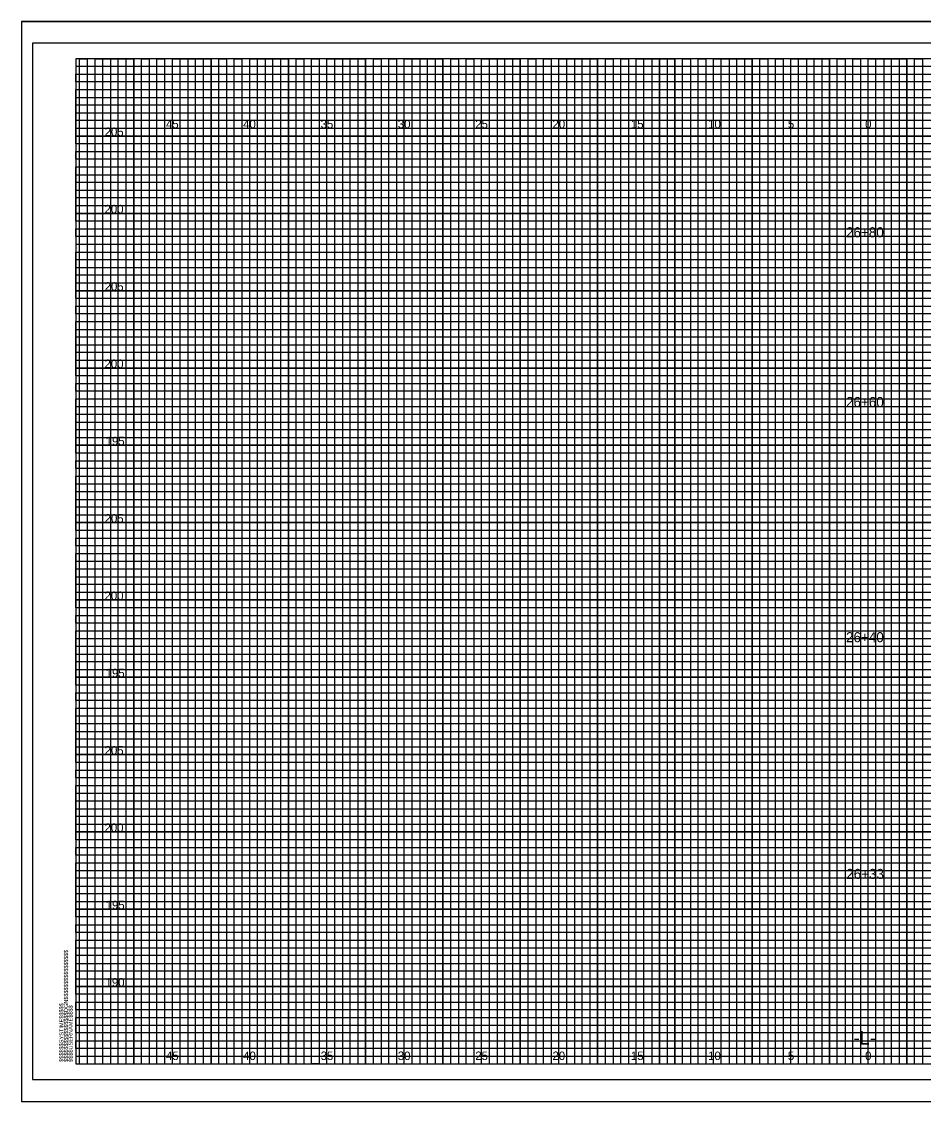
# Model space of a CAD drawing. Extents: x -4 to 103, y -2 to 6583.
# Drawn here: x -3.5 to 54.8, y 1626.6 to 1696.4 of the extents above; entities that cross this region are included whole.
import ezdxf

# ---------------------------------------------------------------- set-up
doc = ezdxf.new("R2010")
doc.units = 0
for name, color, linetype in [('Prop XS Alignment Label', 7, 'Continuous'), ('Prop XS Elevation Labels', 7, 'Continuous'), ('Prop XS Offset Labels', 7, 'Continuous'), ('Prop XS Station Labels', 7, 'Continuous'), ('Sheet Cross Section CELL', 7, 'Continuous'), ('Sheet Cross Section Grid Major CELL', 7, 'Continuous'), ('Sheet Cross Section Grid Middle CELL', 7, 'Continuous'), ('Sheet Cutting Line CELL', 7, 'Continuous'), ('Sheet DOT Grid CELL', 7, 'Continuous'), ('Sheet Plot Border Inside CELL', 7, 'Continuous'), ('Sheet Plot Border Outside CELL', 7, 'Continuous')]:
    doc.layers.add(name, color=color, linetype=linetype)

msp = doc.modelspace()

# ---------------------------------------------------------------- linework, layer by layer
at = {"layer": 'Sheet Cross Section CELL'}
msp.add_lwpolyline([(102.5, 1693.975), (0, 1693.975), (0, 1628.975), (102.5, 1628.975)], close=True, dxfattribs=at)
at = {"layer": 'Sheet Cross Section Grid Major CELL'}
for points in [[(1.25, 1628.975), (1.25, 1693.975), (3.75, 1693.975), (3.75, 1628.975), (6.25, 1628.975), (6.25, 1693.975), (8.75, 1693.975), (8.75, 1628.975), (11.25, 1628.975), (11.25, 1693.975), (13.75, 1693.975), (13.75, 1628.975), (16.25, 1628.975), (16.25, 1693.975), (18.75, 1693.975), (18.75, 1628.975), (21.25, 1628.975), (21.25, 1693.975), (23.75, 1693.975), (23.75, 1628.975), (26.25, 1628.975), (26.25, 1693.975), (28.75, 1693.975), (28.75, 1628.975), (31.25, 1628.975), (31.25, 1693.975), (33.75, 1693.975), (33.75, 1628.975), (36.25, 1628.975), (36.25, 1693.975), (38.75, 1693.975), (38.75, 1628.975), (41.25, 1628.975), (41.25, 1693.975), (43.75, 1693.975), (43.75, 1628.975), (46.25, 1628.975), (46.25, 1693.975), (48.75, 1693.975), (48.75, 1628.975), (51.25, 1628.975), (51.25, 1693.975), (53.75, 1693.975), (53.75, 1628.975)], [(102.5, 1688.975), (0, 1688.975), (0, 1691.475), (74.25, 1691.475)], [(102.5, 1683.975), (0, 1683.975), (0, 1686.475), (102.5, 1686.475)], [(102.5, 1678.975), (0, 1678.975), (0, 1681.475), (102.5, 1681.475)], [(102.5, 1673.975), (0, 1673.975), (0, 1676.475), (102.5, 1676.475)], [(102.5, 1668.975), (0, 1668.975), (0, 1671.475), (102.5, 1671.475)], [(102.5, 1663.975), (0, 1663.975), (0, 1666.475), (102.5, 1666.475)], [(102.5, 1658.975), (0, 1658.975), (0, 1661.475), (102.5, 1661.475)], [(102.5, 1653.975), (0, 1653.975), (0, 1656.475), (102.5, 1656.475)], [(102.5, 1648.975), (0, 1648.975), (0, 1651.475), (102.5, 1651.475)], [(102.5, 1643.975), (0, 1643.975), (0, 1646.475), (102.5, 1646.475)], [(102.5, 1638.975), (0, 1638.975), (0, 1641.475), (102.5, 1641.475)], [(102.5, 1633.975), (0, 1633.975), (0, 1636.475), (102.5, 1636.475)], [(0, 1631.475), (102.5, 1631.475)]]:
    msp.add_lwpolyline(points, dxfattribs=at)
at = {"layer": 'Sheet Cross Section Grid Middle CELL'}
for points in [[(0.25, 1628.975), (0.25, 1693.975), (0.75, 1693.975), (0.75, 1628.975), (1.75, 1628.975), (1.75, 1693.975), (2.25, 1693.975), (2.25, 1628.975), (2.75, 1628.975), (2.75, 1693.975), (3.25, 1693.975), (3.25, 1628.975), (4.25, 1628.975), (4.25, 1693.975), (4.75, 1693.975), (4.75, 1628.975), (5.25, 1628.975), (5.25, 1693.975), (5.75, 1693.975), (5.75, 1628.975), (6.75, 1628.975), (6.75, 1693.975), (7.25, 1693.975), (7.25, 1628.975), (7.75, 1628.975), (7.75, 1693.975), (8.25, 1693.975), (8.25, 1628.975), (9.25, 1628.975), (9.25, 1693.975), (9.75, 1693.975), (9.75, 1628.975), (10.25, 1628.975), (10.25, 1693.975), (10.75, 1693.975), (10.75, 1628.975), (11.75, 1628.975), (11.75, 1693.975), (12.25, 1693.975), (12.25, 1628.975), (12.75, 1628.975), (12.75, 1693.975), (13.25, 1693.975), (13.25, 1628.975), (14.25, 1628.975), (14.25, 1693.975), (14.75, 1693.975), (14.75, 1628.975), (15.75, 1628.975), (15.25, 1628.975), (15.25, 1693.975), (15.75, 1693.975), (15.75, 1628.975), (16.75, 1628.975), (16.75, 1693.975), (17.25, 1693.975), (17.25, 1628.975), (17.75, 1628.975), (17.75, 1693.975), (18.25, 1693.975), (18.25, 1628.975), (19.25, 1628.975), (19.25, 1693.975), (19.75, 1693.975), (19.75, 1628.975), (20.25, 1628.975), (20.25, 1693.975), (20.75, 1693.975), (20.75, 1628.975), (21.75, 1628.975), (21.75, 1693.975), (22.25, 1693.975), (22.25, 1628.975), (22.75, 1628.975), (22.75, 1693.975), (23.25, 1693.975), (23.25, 1628.975), (24.25, 1628.975), (24.25, 1693.975), (24.75, 1693.975), (24.75, 1628.975), (25.25, 1628.975), (25.25, 1693.975), (25.75, 1693.975), (25.75, 1628.975), (26.75, 1628.975), (26.75, 1693.975), (27.25, 1693.975), (27.25, 1628.975), (27.75, 1628.975), (27.75, 1693.975), (28.25, 1693.975), (28.25, 1628.975), (29.25, 1628.975), (29.25, 1693.975), (29.75, 1693.975), (29.75, 1628.975), (30.25, 1628.975), (30.25, 1693.975), (30.75, 1693.975), (30.75, 1628.975)], [(30.75, 1628.975), (31.75, 1628.975), (31.75, 1693.975), (32.25, 1693.975), (32.25, 1628.975), (32.75, 1628.975), (32.75, 1693.975), (33.25, 1693.975), (33.25, 1628.975), (34.25, 1628.975), (34.25, 1693.975), (34.75, 1693.975), (34.75, 1628.975), (35.25, 1628.975), (35.25, 1693.975), (35.75, 1693.975), (35.75, 1628.975), (36.75, 1628.975), (36.75, 1693.975), (37.25, 1693.975), (37.25, 1628.975), (37.75, 1628.975), (37.75, 1693.975), (37.75, 1628.975)], [(38.25, 1693.975), (38.25, 1628.975), (39.25, 1628.975), (39.25, 1693.975), (39.75, 1693.975), (39.75, 1628.975), (40.25, 1628.975), (40.25, 1693.975), (40.75, 1693.975), (40.75, 1628.975), (41.75, 1628.975), (41.75, 1693.975), (42.25, 1693.975), (42.25, 1628.975), (42.75, 1628.975), (42.75, 1693.975), (43.25, 1693.975), (43.25, 1628.975), (43.75, 1628.975), (44.25, 1628.975), (44.25, 1693.975), (44.75, 1693.975), (44.75, 1628.975), (45.25, 1628.975), (45.25, 1693.975), (45.75, 1693.975), (45.75, 1628.975), (46.75, 1628.975), (46.75, 1693.975), (47.25, 1693.975), (47.25, 1628.975), (47.75, 1628.975), (47.75, 1693.975), (48.25, 1693.975), (48.25, 1628.975), (49.25, 1628.975), (49.25, 1693.975), (49.75, 1693.975), (49.75, 1628.975), (50.25, 1628.975), (50.25, 1693.975), (50.75, 1693.975), (50.75, 1628.975), (51.75, 1628.975), (51.75, 1693.975), (52.25, 1693.975), (52.25, 1628.975), (52.75, 1628.975), (52.75, 1693.975), (53.25, 1693.975), (53.25, 1628.975), (54.25, 1628.975), (54.25, 1693.975), (54.75, 1693.975), (54.75, 1628.975), (55.25, 1628.975)], [(0, 1690.975), (0, 1691.975), (74.25, 1691.975), (74.25, 1692.475), (0, 1692.475), (0, 1692.975), (74.25, 1692.975), (74.25, 1693.475), (0, 1693.475)], [(102.5, 1690.975), (0, 1690.975)], [(102.5, 1689.975), (0, 1689.975), (0, 1690.475), (102.5, 1690.475)], [(102.5, 1688.475), (0, 1688.475), (0, 1689.475), (102.5, 1689.475)], [(102.5, 1687.475), (0, 1687.475), (0, 1687.975), (102.5, 1687.975)], [(102.5, 1685.975), (0, 1685.975), (0, 1686.975), (102.5, 1686.975)], [(102.5, 1684.975), (0, 1684.975), (0, 1685.475), (102.5, 1685.475)], [(102.5, 1683.475), (0, 1683.475), (0, 1684.475), (102.5, 1684.475)], [(102.5, 1682.475), (0, 1682.475), (0, 1682.975), (102.5, 1682.975)], [(0, 1681.975), (102.5, 1681.975)], [(102.5, 1680.975), (0, 1680.975)], [(102.5, 1679.975), (0, 1679.975), (0, 1680.475), (102.5, 1680.475)], [(102.5, 1678.475), (0, 1678.475), (0, 1679.475), (102.5, 1679.475)], [(102.5, 1677.475), (0, 1677.475), (0, 1677.975), (102.5, 1677.975)], [(102.5, 1675.975), (0, 1675.975), (0, 1676.975), (102.5, 1676.975)], [(102.5, 1674.975), (0, 1674.975), (0, 1675.475), (102.5, 1675.475)], [(102.5, 1673.475), (0, 1673.475), (0, 1674.475), (102.5, 1674.475)], [(102.5, 1672.475), (0, 1672.475), (0, 1672.975), (102.5, 1672.975)], [(102.5, 1670.975), (0, 1670.975), (0, 1671.975), (102.5, 1671.975)], [(102.5, 1669.975), (0, 1669.975), (0, 1670.475), (102.5, 1670.475)], [(102.5, 1668.475), (0, 1668.475), (0, 1669.475), (102.5, 1669.475)], [(102.5, 1667.475), (0, 1667.475), (0, 1667.975), (102.5, 1667.975)], [(102.5, 1665.975), (0, 1665.975), (0, 1666.975), (102.5, 1666.975)], [(102.5, 1664.975), (0, 1664.975), (0, 1665.475), (102.5, 1665.475)], [(102.5, 1663.475), (0, 1663.475), (0, 1664.475), (102.5, 1664.475)], [(102.5, 1662.475), (0, 1662.475), (0, 1662.975), (102.5, 1662.975)], [(102.5, 1660.975), (0, 1660.975), (0, 1661.975), (102.5, 1661.975)], [(102.5, 1659.975), (0, 1659.975), (0, 1660.475)], [(0, 1660.475), (102.5, 1660.475)], [(102.5, 1658.475), (0, 1658.475), (0, 1659.475), (102.5, 1659.475)], [(102.5, 1657.475), (0, 1657.475), (0, 1657.975), (102.5, 1657.975)], [(102.5, 1655.975), (0, 1655.975), (0, 1656.975), (102.5, 1656.975)], [(102.5, 1654.975), (0, 1654.975), (0, 1655.475), (102.5, 1655.475)], [(102.5, 1653.475), (0, 1653.475), (0, 1654.475), (102.5, 1654.475)], [(102.5, 1652.475), (0, 1652.475), (0, 1652.975), (102.5, 1652.975)], [(102.5, 1650.975), (0, 1650.975), (0, 1651.975), (102.5, 1651.975)], [(102.5, 1649.975), (0, 1649.975), (0, 1650.475), (102.5, 1650.475)], [(102.5, 1648.475), (0, 1648.475), (0, 1649.475), (102.5, 1649.475)], [(102.5, 1647.475), (0, 1647.475), (0, 1647.975), (102.5, 1647.975)], [(102.5, 1645.975), (0, 1645.975), (0, 1646.975), (102.5, 1646.975)], [(102.5, 1644.975), (0, 1644.975), (0, 1645.475), (102.5, 1645.475)], [(102.5, 1643.475), (0, 1643.475), (0, 1644.475), (102.5, 1644.475)], [(102.5, 1642.475), (0, 1642.475), (0, 1642.975), (102.5, 1642.975)], [(102.5, 1640.975), (0, 1640.975), (0, 1641.975), (102.5, 1641.975)], [(102.5, 1639.975), (0, 1639.975), (0, 1640.475), (102.5, 1640.475)], [(102.5, 1638.475), (0, 1638.475), (0, 1639.475), (102.5, 1639.475)], [(102.5, 1637.475), (0, 1637.475), (0, 1637.975), (102.5, 1637.975)], [(102.5, 1635.975), (0, 1635.975), (0, 1636.975), (102.5, 1636.975)], [(102.5, 1634.975), (0, 1634.975), (0, 1635.475), (102.5, 1635.475)], [(102.5, 1633.475), (0, 1633.475), (0, 1634.475), (102.5, 1634.475)], [(102.5, 1632.475), (0, 1632.475), (0, 1632.975), (102.5, 1632.975)], [(102.5, 1630.975), (0, 1630.975), (0, 1631.975), (102.5, 1631.975)], [(102.5, 1629.975), (0, 1629.975), (0, 1630.475), (102.5, 1630.475)], [(0, 1629.475), (102.5, 1629.475)]]:
    msp.add_lwpolyline(points, dxfattribs=at)
at = {"layer": 'Sheet Cutting Line CELL'}
for p, q in [((-3.5, 1696.375), (103.4, 1696.375)), ((-3.5, 1696.375), (-3.5, 1626.55)), ((-3.5, 1626.55), (103.4, 1626.55))]:
    msp.add_line(p, q, dxfattribs=at)
at = {"layer": 'Sheet DOT Grid CELL'}
for p, q in [((1.25, 1628.975), (1.25, 1693.975)), ((3.75, 1628.975), (3.75, 1693.975)), ((6.25, 1628.975), (6.25, 1693.975)), ((8.75, 1628.975), (8.75, 1693.975)), ((11.25, 1628.975), (11.25, 1693.975)), ((13.75, 1628.975), (13.75, 1693.975)), ((16.25, 1628.975), (16.25, 1693.975)), ((18.75, 1628.975), (18.75, 1693.975)), ((21.25, 1628.975), (21.25, 1693.975)), ((23.75, 1628.975), (23.75, 1693.975)), ((26.25, 1628.975), (26.25, 1693.975)), ((28.75, 1628.975), (28.75, 1693.975)), ((31.25, 1628.975), (31.25, 1693.975)), ((33.75, 1628.975), (33.75, 1693.975)), ((36.25, 1628.975), (36.25, 1693.975)), ((38.75, 1628.975), (38.75, 1693.975)), ((41.25, 1628.975), (41.25, 1693.975)), ((43.75, 1628.975), (43.75, 1693.975)), ((46.25, 1628.975), (46.25, 1693.975)), ((48.75, 1628.975), (48.75, 1693.975)), ((51.25, 1628.975), (51.25, 1693.975)), ((53.75, 1628.975), (53.75, 1693.975)), ((0, 1691.475), (74.25, 1691.475)), ((0, 1688.975), (102.5, 1688.975)), ((0, 1686.475), (102.5, 1686.475)), ((0, 1683.975), (102.5, 1683.975)), ((0, 1681.475), (102.5, 1681.475)), ((0, 1678.975), (102.5, 1678.975)), ((0, 1676.475), (102.5, 1676.475)), ((0, 1673.975), (102.5, 1673.975)), ((0, 1671.475), (102.5, 1671.475)), ((0, 1668.975), (102.5, 1668.975)), ((0, 1666.475), (102.5, 1666.475)), ((0, 1663.975), (102.5, 1663.975)), ((0, 1661.475), (102.5, 1661.475)), ((0, 1658.975), (102.5, 1658.975)), ((0, 1656.475), (102.5, 1656.475)), ((0, 1653.975), (102.5, 1653.975)), ((0, 1651.475), (102.5, 1651.475)), ((0, 1648.975), (102.5, 1648.975)), ((0, 1646.475), (102.5, 1646.475)), ((0, 1643.975), (102.5, 1643.975)), ((0, 1641.475), (102.5, 1641.475)), ((0, 1638.975), (102.5, 1638.975)), ((0, 1636.475), (102.5, 1636.475)), ((0, 1633.975), (102.5, 1633.975)), ((0, 1631.475), (102.5, 1631.475))]:
    msp.add_line(p, q, dxfattribs=at)
at = {"layer": 'Sheet Plot Border Inside CELL'}
msp.add_lwpolyline([(103, 1694.975), (-2.8, 1694.975), (-2.8, 1627.975), (103, 1627.975)], close=True, dxfattribs=at)
at = {"layer": 'Sheet Plot Border Outside CELL'}
msp.add_lwpolyline([(103.4, 1696.375), (-3.5, 1696.375), (-3.5, 1626.55), (103.4, 1626.55)], close=True, dxfattribs=at)

# ---------------------------------------------------------------- texts
at = {"layer": 'Prop XS Alignment Label'}
msp.add_text('-L-', height=0.875, dxfattribs=at).set_placement((50.307, 1630.225))
at = {"layer": 'Prop XS Elevation Labels'}
for s, p in [('205', (1.872, 1688.975)), ('200', (1.864, 1683.975)), ('205', (1.872, 1678.975)), ('200', (1.864, 1673.975)), ('195', (1.938, 1668.975)), ('205', (1.872, 1663.975)), ('200', (1.864, 1658.975)), ('195', (1.938, 1653.975)), ('205', (1.872, 1648.975)), ('200', (1.864, 1643.975)), ('195', (1.938, 1638.975)), ('190', (1.93, 1633.975))]:
    msp.add_text(s, height=0.55, dxfattribs=at).set_placement(p)
at = {"layer": 'Prop XS Offset Labels'}
for s, p in [('45', (5.84, 1689.475)), ('40', (10.831, 1689.475)), ('35', (15.84, 1689.475)), ('30', (20.831, 1689.475)), ('25', (25.84, 1689.475)), ('20', (30.831, 1689.475)), ('15', (35.906, 1689.475)), ('10', (40.897, 1689.475)), ('5', (46.057, 1689.475)), ('0', (51.049, 1689.475)), ('0', (51.049, 1689.475)), ('45', (5.84, 1629.225)), ('40', (10.831, 1629.225)), ('35', (15.84, 1629.225)), ('30', (20.831, 1629.225)), ('25', (25.84, 1629.225)), ('20', (30.831, 1629.225)), ('15', (35.906, 1629.225)), ('10', (40.897, 1629.225)), ('5', (46.057, 1629.225)), ('0', (51.049, 1629.225)), ('0', (51.049, 1629.225))]:
    msp.add_text(s, height=0.55, dxfattribs=at).set_placement(p)
at = {"layer": 'Prop XS Station Labels'}
for s, p in [('26+80', (49.816, 1682.426)), ('26+60', (49.816, 1671.45)), ('26+40', (49.816, 1656.242)), ('26+33', (49.83, 1640.936))]:
    msp.add_text(s, height=0.65, dxfattribs=at).set_placement(p)
at = {"layer": 'Sheet Cross Section CELL'}
for s, p in [('$$$$$$$$$$$$$$$$DGN$$$$$$$$$$$$$$$$', (-0.5, 1629.1)), ('$$$$$$SYSTIME$$$$$', (-0.797, 1629.1)), ('$$$$USERNAME$$$$', (-0.2, 1629.1))]:
    msp.add_text(s, height=0.2625, rotation=90, dxfattribs=at).set_placement(p)
at = {"layer": 'Sheet Cross Section Grid Major CELL'}
msp.add_text('040397', height=0.0025, rotation=90, dxfattribs=at).set_placement((-0.001, 1693.961))

doc.saveas('drawing.dxf')
